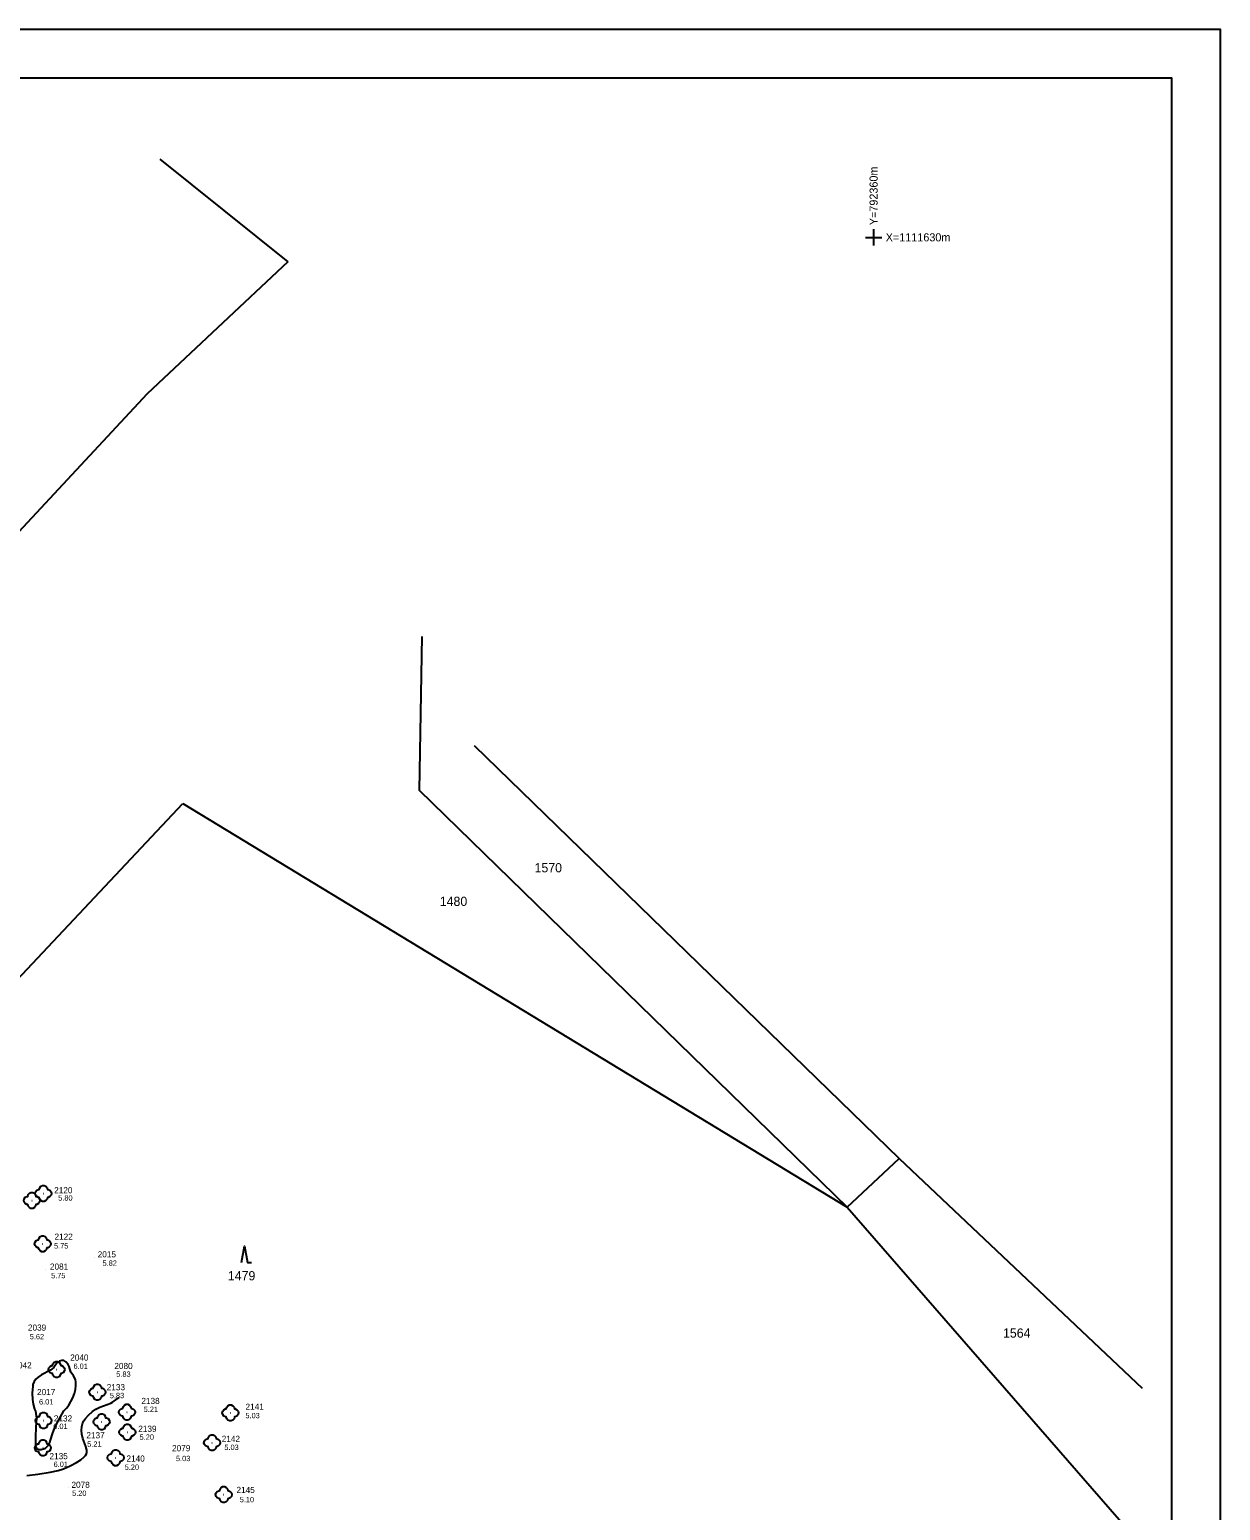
# Model space of a CAD drawing. Extents: x -792549 to -792339, y -1111914 to -1111617.
# Drawn here: x -792412.2 to -792338.6, y -1111708.7 to -1111617.2 of the extents above; entities that cross this region are included whole.
import ezdxf

# ---------------------------------------------------------------- set-up
doc = ezdxf.new("R2010")
doc.units = 0
for name, color, linetype in [('Vrstva 1', 7, 'Continuous'), ('Vrstva 24', 7, 'Continuous'), ('Vrstva 32', 7, 'Continuous'), ('Vrstva 33', 7, 'Continuous'), ('Vrstva 41', 7, 'Continuous'), ('Vrstva 42', 7, 'Continuous'), ('Vrstva 44', 7, 'Continuous'), ('Vrstva 45', 7, 'Continuous'), ('Vrstva 48', 7, 'Continuous'), ('Vrstva 49', 7, 'Continuous'), ('Vrstva 50', 7, 'Continuous'), ('Vrstva 60', 7, 'Continuous')]:
    doc.layers.add(name, color=color, linetype=linetype)

# ---------------------------------------------------------------- blocks, each defined once
blk = doc.blocks.new('3$0800')
at = {"layer": 'Vrstva 1'}
blk.add_lwpolyline([(-7.5, 0), (0, 40), (7.5, 0), (17.5, 0)], dxfattribs=at)
blk = doc.blocks.new('$408')
at = {"layer": 'Vrstva 1'}
for p, q in [((-20, 0), (20, 0)), ((0, 20), (0, -20))]:
    blk.add_line(p, q, dxfattribs=at)
blk = doc.blocks.new('3$1301')
at = {"layer": 'Vrstva 1'}
for points in [[(20, 0), (19, -4.3), (16.2, -7.8), (12.2, -9.7), (10, -10), (9, -14.3), (6.2, -17.8), (2.2, -19.7), (-2.3, -19.7), (-6.3, -17.8), (-9.1, -14.3), (-10.1, -10), (-12.3, -9.7), (-16.3, -7.8), (-19.1, -4.3), (-20.1, 0), (-19.1, 4.3), (-16.3, 7.8), (-12.3, 9.7), (-10.1, 10), (-9.1, 14.3), (-6.3, 17.8), (-2.3, 19.7), (2.2, 19.7), (6.2, 17.8), (9, 14.3), (10, 10), (12.2, 9.7), (16.2, 7.8), (19, 4.3), (20, 0)], [(-0.5, 0), (0, 0), (0.5, 0)]]:
    blk.add_lwpolyline(points, dxfattribs=at)
blk = doc.blocks.new('SC6231')
at = {"layer": 'Vrstva 1'}
blk.add_line((0, 0), (0, 0), dxfattribs=at)

msp = doc.modelspace()

# ---------------------------------------------------------------- linework, layer by layer
at = {"layer": 'Vrstva 24'}
msp.add_lwpolyline([(-792545.564, -1111620.164), (-792545.564, -1111911.164), (-792341.564, -1111911.164), (-792341.564, -1111620.164)], close=True, dxfattribs=at)
at = {"layer": 'Vrstva 32'}
for points in [[(-792410.049, -1111702.511), (-792409.899, -1111702.352), (-792409.75, -1111702.157), (-792409.616, -1111701.943), (-792409.494, -1111701.701), (-792409.399, -1111701.445), (-792409.337, -1111701.192), (-792409.306, -1111700.94), (-792409.307, -1111700.726), (-792409.326, -1111700.6), (-792409.367, -1111700.492), (-792409.463, -1111700.345), (-792409.628, -1111700.115), (-792409.736, -1111699.767), (-792409.798, -1111699.647), (-792409.923, -1111699.48), (-792410.048, -1111699.409), (-792410.178, -1111699.396), (-792410.316, -1111699.438), (-792410.448, -1111699.526), (-792410.505, -1111699.578), (-792410.558, -1111699.643), (-792410.683, -1111699.841), (-792410.874, -1111699.992), (-792411.441, -1111700.288), (-792411.642, -1111700.424), (-792411.782, -1111700.554), (-792411.89, -1111700.7), (-792411.964, -1111700.892), (-792411.977, -1111700.989)], [(-792411.977, -1111700.989), (-792412.008, -1111701.419), (-792411.989, -1111701.805), (-792411.942, -1111702.108), (-792411.859, -1111702.41), (-792411.805, -1111702.541)], [(-792411.805, -1111702.541), (-792411.753, -1111702.959), (-792411.783, -1111703.515), (-792411.817, -1111704.142), (-792411.797, -1111704.638)], [(-792410.887, -1111704.322), (-792410.748, -1111703.929), (-792410.609, -1111703.535), (-792410.361, -1111703.076), (-792410.049, -1111702.511)], [(-792411.797, -1111704.638), (-792411.799, -1111704.652), (-792411.787, -1111704.746), (-792411.747, -1111704.821), (-792411.698, -1111704.868), (-792411.579, -1111704.897), (-792411.455, -1111704.892), (-792411.258, -1111704.839), (-792411.19, -1111704.813), (-792411.079, -1111704.721), (-792411.012, -1111704.631), (-792410.928, -1111704.476), (-792410.888, -1111704.332), (-792410.887, -1111704.322)]]:
    msp.add_lwpolyline(points, dxfattribs=at)
at = {"layer": 'Vrstva 33'}
msp.add_lwpolyline([(-792412.336, -1111706.516), (-792411.661, -1111706.433), (-792410.895, -1111706.305), (-792410.413, -1111706.196), (-792410.079, -1111706.086), (-792409.672, -1111705.913), (-792409.282, -1111705.71), (-792409.002, -1111705.532), (-792408.794, -1111705.364), (-792408.711, -1111705.273), (-792408.646, -1111705.165), (-792408.626, -1111705.068), (-792408.635, -1111704.933), (-792408.699, -1111704.706), (-792408.877, -1111704.217), (-792408.94, -1111703.945), (-792408.957, -1111703.721), (-792408.944, -1111703.483), (-792408.908, -1111703.308), (-792408.846, -1111703.157), (-792408.723, -1111702.979), (-792408.532, -1111702.774), (-792408.284, -1111702.561), (-792408.069, -1111702.409), (-792407.829, -1111702.278), (-792407.16, -1111702.042), (-792407.051, -1111701.98), (-792406.631, -1111701.678)], dxfattribs=at)
at = {"layer": 'Vrstva 41'}
for p, q in [((-792404.13, -1111625.165), (-792396.21, -1111631.51)), ((-792456.34, -1111722.07), (-792402.71, -1111664.98)), ((-792361.64, -1111689.93), (-792358.41, -1111686.91))]:
    msp.add_line(p, q, dxfattribs=at)
for points in [[(-792396.21, -1111631.51), (-792404.9, -1111639.66), (-792454.29, -1111692.72), (-792461.78, -1111700.29), (-792461.99, -1111689.5), (-792462.65, -1111684.23), (-792458.31, -1111684.1), (-792457.6, -1111689.12), (-792454.29, -1111692.72)], [(-792387.93, -1111654.66), (-792388.1, -1111664.15), (-792361.64, -1111689.93)], [(-792384.7, -1111661.39), (-792358.41, -1111686.91), (-792343.404, -1111701.103)], [(-792402.71, -1111664.98), (-792361.64, -1111689.93), (-792344.27, -1111709.86), (-792345.69, -1111715.24), (-792370.08, -1111711.34), (-792389.29, -1111709.91)]]:
    msp.add_lwpolyline(points, dxfattribs=at)
at = {"layer": 'Vrstva 60'}
msp.add_lwpolyline([(-792548.564, -1111617.164), (-792548.564, -1111914.164), (-792338.564, -1111914.164), (-792338.564, -1111617.164), (-792548.564, -1111617.164)], dxfattribs=at)

# ---------------------------------------------------------------- block references
at = {"layer": 'Vrstva 42', "xscale": 0.025, "yscale": 0.025000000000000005}
msp.add_blockref('3$0800', (-792398.888, -1111693.341), dxfattribs=at)
at = {"layer": 'Vrstva 44', "xscale": 0.025, "yscale": 0.025000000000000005}
for p in [(-792412.03, -1111689.51), (-792411.32, -1111689.08), (-792411.36, -1111692.19), (-792410.5, -1111699.96), (-792407.98, -1111701.36), (-792406.15, -1111702.6), (-792411.31, -1111703.11), (-792407.72, -1111703.19), (-792399.76, -1111702.64), (-792406.13, -1111703.83), (-792411.35, -1111704.8), (-792400.89, -1111704.48), (-792406.85, -1111705.41), (-792400.17, -1111707.69)]:
    msp.add_blockref('3$1301', p, dxfattribs=at)
at = {"layer": 'Vrstva 45', "xscale": 0.025, "yscale": 0.025000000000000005}
msp.add_blockref('$408', (-792360, -1111630), dxfattribs=at)
at = {"layer": 'Vrstva 48', "xscale": 0.1, "yscale": 0.10000000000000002}
for p in [(-792411.32, -1111689.08), (-792412.03, -1111689.51), (-792411.36, -1111692.19), (-792411.2, -1111693.78), (-792408.14, -1111693.02), (-792410.5, -1111699.96), (-792411.9, -1111700.95), (-792407.26, -1111700.47), (-792407.98, -1111701.36), (-792406.15, -1111702.6), (-792399.76, -1111702.64), (-792411.31, -1111703.11), (-792407.72, -1111703.19), (-792406.13, -1111703.83), (-792411.35, -1111704.8), (-792402.26, -1111704.36), (-792400.89, -1111704.48), (-792406.85, -1111705.41), (-792409.76, -1111707.26), (-792400.17, -1111707.69)]:
    msp.add_blockref('SC6231', p, dxfattribs=at)

# ---------------------------------------------------------------- texts
at = {"layer": 'Vrstva 42'}
for s, p in [('1570', (-792380.958, -1111669.238)), ('1480', (-792386.816, -1111671.314)), ('1479', (-792399.915, -1111694.45)), ('1564', (-792352, -1111697.99))]:
    msp.add_text(s, height=0.57, dxfattribs=at).set_placement(p)
at = {"layer": 'Vrstva 45'}
msp.add_text('Y=792360m', height=0.5, rotation=90.012, dxfattribs=at).set_placement((-792359.75, -1111629.25))
msp.add_text('X=1111630m', height=0.5, dxfattribs=at).set_placement((-792359.25, -1111630.25))
at = {"layer": 'Vrstva 49'}
for s, p in [('2120', (-792410.653, -1111689.07)), ('2122', (-792410.633, -1111691.94)), ('2015', (-792407.963, -1111693.03)), ('2081', (-792410.915, -1111693.79)), ('2039', (-792412.275, -1111697.56)), ('2040', (-792409.663, -1111699.41)), ('2042', (-792413.173, -1111699.89)), ('2080', (-792406.933, -1111699.93)), ('2017', (-792411.713, -1111701.54)), ('2133', (-792407.403, -1111701.24)), ('2138', (-792405.263, -1111702.09)), ('2141', (-792398.825, -1111702.45)), ('2132', (-792410.673, -1111703.17)), ('2137', (-792408.663, -1111704.21)), ('2139', (-792405.455, -1111703.81)), ('2079', (-792403.365, -1111705.01)), ('2142', (-792400.293, -1111704.43)), ('2135', (-792410.943, -1111705.5)), ('2140', (-792406.183, -1111705.65)), ('2078', (-792409.583, -1111707.27)), ('2145', (-792399.383, -1111707.59))]:
    msp.add_text(s, height=0.38, dxfattribs=at).set_placement(p)
at = {"layer": 'Vrstva 50'}
for s, p in [('5.80', (-792410.403, -1111689.52)), ('5.75', (-792410.663, -1111692.48)), ('5.82', (-792407.663, -1111693.55)), ('5.75', (-792410.843, -1111694.32)), ('5.62', (-792412.163, -1111698.09)), ('6.01', (-792409.459, -1111699.92)), ('5.83', (-792406.813, -1111700.41)), ('6.01', (-792411.589, -1111702.12)), ('5.83', (-792407.213, -1111701.73)), ('5.21', (-792405.119, -1111702.58)), ('5.03', (-792398.833, -1111702.97)), ('6.01', (-792410.709, -1111703.63)), ('5.21', (-792408.609, -1111704.73)), ('5.20', (-792405.373, -1111704.3)), ('5.03', (-792400.133, -1111704.93)), ('6.01', (-792410.689, -1111705.98)), ('5.03', (-792403.123, -1111705.62)), ('5.20', (-792406.293, -1111706.16)), ('5.20', (-792409.543, -1111707.77)), ('5.10', (-792399.183, -1111708.16))]:
    msp.add_text(s, height=0.33, dxfattribs=at).set_placement(p)

doc.saveas('drawing.dxf')
